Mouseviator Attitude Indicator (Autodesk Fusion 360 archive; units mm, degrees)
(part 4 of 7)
sketch "Board outlines" plane through (0, 39, 0) normal (0, 1, 0) x axis (1, 0, 0)
  line L1 (36.0921, -32.5978) -> (36.0921, 0.9022)
  line L2 (5.0921, -32.5978) -> (36.0921, -32.5978)
  line L3 (5.0921, 0.9022) -> (5.0921, -32.5978)
  line L4 (36.0921, 0.9022) -> (5.0921, 0.9022)
  line L5 (36.0921, 0.9022) -> (5.0921, -32.5978)
  line L6 (5.0921, 0.9022) -> (36.0921, -32.5978)
  line L7 (-0.4082, -32.5804) -> (-0.4082, 0.9196)
  line L8 (-31.4082, -32.5804) -> (-0.4082, -32.5804)
  line L9 (-31.4082, 0.9196) -> (-31.4082, -32.5804)
  line L10 (-0.4082, 0.9196) -> (-31.4082, 0.9196)
  line L11 (-0.4082, 0.9196) -> (-31.4082, -32.5804)
  line L12 (-31.4082, 0.9196) -> (-0.4082, -32.5804)
  line L13 (-36.4994, -34.1766) -> (-41.1157, -22.3885)
  line L14 (-26.5185, -40.8706) -> (-34.1546, -36.8093)
  line L15 (24.1231, -41.4655) -> (-24.1331, -41.4655)
  line L16 (33.6166, -37.0564) -> (26.5251, -40.8618)
  line L17 (41.1157, -22.3885) -> (36.4994, -34.1766)
  line L18 (41.4655, 20.5361) -> (41.4655, -20.5361)
  line L19 (36.4994, 34.1766) -> (41.1157, 22.3885)
  line L20 (23.2139, 41.1177) -> (33.6166, 37.0564)
  curve K1 (21.3665, 41.4655) -> (21.9088, 41.4365)
  line L21 (-28.9018, 41.4655) -> (21.3665, 41.4655)
  line L22 (-41.4655, -20.5361) -> (-41.4655, 28.9018)
  curve K2 (-41.4365, -21.0784) -> (-41.4655, -20.5361)
  line L23 (-40, -14) -> (-35, -14)
  line L24 (-40, 12) -> (-40, -14)
  line L25 (-35, 12) -> (-40, 12)
  line L26 (-35, -14) -> (-35, 12)
  line L27 (34.1616, 34.6741) -> (38.4785, 23.6504)
  line L28 (23.7487, 38.7393) -> (34.1616, 34.6741)
  line L29 (21.8646, 33.9133) -> (23.7487, 38.7393)
  line L30 (30.1616, 30.6741) -> (21.8646, 33.9133)
  line L31 (33.6522, 21.7604) -> (30.1616, 30.6741)
  line L32 (38.4785, 23.6504) -> (33.6522, 21.7604)
  circle C1 centre (7.0921, -1.0978) radius 1.375
  circle C2 centre (34.0921, -1.0978) radius 1.375
  circle C3 centre (34.0921, -30.5978) radius 1.375
  circle C4 centre (7.0921, -30.5978) radius 1.375
  circle C5 centre (-29.4082, -1.0804) radius 1.375
  circle C6 centre (-2.4082, -1.0804) radius 1.375
  circle C7 centre (-2.4082, -30.5804) radius 1.375
  circle C8 centre (-29.4082, -30.5804) radius 1.375
  circle C9 centre (-20, 14) radius 10
  circle C10 centre (18.76, 36.96) radius 1.4
  circle C11 centre (-37.3525, 16.6048) radius 1.4
  circle C12 centre (-18.76, -36.96) radius 1.4
  circle C13 centre (36.96, -18.76) radius 1.4
  circle C14 centre (18.76, -36.96) radius 1.4
  circle C15 centre (-36.96, -18.76) radius 1.4
  circle C16 centre (-17.3319, 36.9825) radius 1.4
  circle C17 centre (36.96, 18.76) radius 1.4
  arc A1 centre (-36.3855, -20.5361) radius 5.08 clockwise from (-41.1157, -22.3885) to (-41.4365, -21.0784)
  arc A2 centre (-31.7692, -32.3242) radius 5.08 clockwise from (-34.1546, -36.8093) to (-36.4994, -34.1766)
  arc A3 centre (-24.1331, -36.3855) radius 5.08 clockwise from (-24.1331, -41.4655) to (-26.5185, -40.8706)
  arc A4 centre (24.1231, -36.3855) radius 5.08 clockwise from (26.5251, -40.8618) to (24.1231, -41.4655)
  arc A5 centre (31.7692, -32.3242) radius 5.08 clockwise from (36.4994, -34.1766) to (33.6166, -37.0564)
  arc A6 centre (36.3855, -20.5361) radius 5.08 clockwise from (41.4655, -20.5361) to (41.1157, -22.3885)
  arc A7 centre (36.3855, 20.5361) radius 5.08 clockwise from (41.1157, 22.3885) to (41.4655, 20.5361)
  arc A8 centre (31.7692, 32.3242) radius 5.08 clockwise from (33.6166, 37.0564) to (36.4994, 34.1766)
  arc A9 centre (21.3665, 36.3855) radius 5.08 clockwise from (21.9088, 41.4365) to (23.2139, 41.1177)
  arc A10 centre (-28.9018, 28.9018) radius 12.5637 clockwise from (-41.4655, 28.9018) to (-28.9018, 41.4655)
  point P3 (36.0921, 0.9022)
  point P4 (5.0921, 0.9022)
  point P6 (5.0921, -32.5978)
  point P9 (7.0921, -1.0978)
  point P11 (-0.4082, 0.9196)
  point P12 (-31.4082, 0.9196)
  point P14 (-31.4082, -32.5804)
  point P17 (-29.4082, -1.0804)
  point P26 (36.96, 18.76)
  point P19 (18.76, 36.96)
  point P10 (-29.4082, -30.5804)
  point P16 (-2.4082, -30.5804)
  point P15 (-2.4082, -1.0804)
  point P7 (34.0921, -1.0978)
  point P8 (34.0921, -30.5978)
  point P2 (7.0921, -30.5978)
  perpendicular L2 L3
  parallel L2 L4
  parallel L1 L3
  horizontal L2
  perpendicular L8 L9
  parallel L8 L10
  parallel L7 L9
  horizontal L8
  horizontal L23
  vertical L24
  horizontal L25
  vertical L26
  parallel L19 L27
  parallel L20 L28
  perpendicular L28 L29
  perpendicular L29 L30
  parallel L27 L31
  perpendicular L31 L32
  dimension "d433_1" distance P3 P4 = 31
  dimension "d434_1" distance P4 P6 = 33.5
  dimension "d435_1" diameter C1 = 2.75
  dimension "d436_1" distance P9 L3 = 2
  dimension "d437_1" distance P9 L4 = 2
  dimension "d442_1" distance P11 P12 = 31
  dimension "d443_1" distance P12 P14 = 33.5
  dimension "d444_1" diameter C5 = 2.75
  dimension "d445_1" distance P17 L9 = 2
  dimension "d446_1" distance P17 L10 = 2
  dimension "d470_1" diameter C9 = 20
  dimension "d478_1" distance P26 L32 = 4
  dimension "d479_1" distance P19 L29 = 4
  dimension "d546" distance P10 L8 = 2
  dimension "d547" distance P16 L8 = 2
  dimension "d548" distance P16 L7 = 2
  dimension "d549" distance P10 L9 = 2
  dimension "d550" distance P15 L10 = 2
  dimension "d551" distance P15 L7 = 2
  dimension "d552" distance P7 L4 = 2
  dimension "d553" distance P7 L1 = 2
  dimension "d554" distance P8 L1 = 2
  dimension "d555" distance P8 L2 = 2
  dimension "d556" distance P2 L2 = 2
  dimension "d557" distance P2 L3 = 2
extrude "Extrude16" add sketch "Board outlines" profile of C1 C2 C3 C4 C5 C6 C7 C8 along normal blind 7 named "d473_1" Side1WallThickness 1.5 named "d472_1"
extrude "Extrude17" cut sketch "Board outlines" profile of C9 no distance stored
fillet "Fillet4" radius 1 named "d477_1"
extrude "Extrude18" add sketch "Board outlines" profile of L27 L28 L29 L30 L31 L32 along normal blind 10 named "d480_1"
extrude "Extrude19" add sketch "Board outlines" profile of L23 L24 L25 L26 along normal blind 10 named "d482_1"
sketch "VCC cutouts" plane through (-40, 0, 0) normal (-1, 0, 0) x axis (0, -1, 0)
  line L1 (-39, 14) -> (-39, -12)
  line L2 (-49, 14) -> (-39, 14)
  line L3 (-49, -12) -> (-49, 14)
  line L4 (-39, -12) -> (-49, -12)
  circle C1 centre (-44, 9) radius 3
  circle C2 centre (-44, -7) radius 3
  circle C3 centre (-44, 1) radius 3
  dimension "d484_1" diameter C1 = 6
  dimension "d485_1" diameter C2 = 6
  dimension "d486_1" diameter C3 = 6
extrude "Extrude20" cut sketch "VCC cutouts" profile of C1 C2 C3 against normal blind 6 named "d487_1"
sketch "Cable cutout 1" plane through (36.5661, 0, -14.3196) normal (-0.9311, 0, 0.3646) x axis (0, -1, 0)
  line L1 (-39, -7.991) -> (-39, -17.5638)
  line L2 (-49, -7.991) -> (-39, -7.991)
  line L3 (-49, -17.5638) -> (-49, -7.991)
  line L4 (-39, -17.5638) -> (-49, -17.5638)
  circle C1 centre (-44, -12.7774) radius 3.5
  dimension "d489_1" diameter C1 = 7
sketch "Cable cutout 2" plane through (14.3806, 0, -36.835) normal (-0.3637, 0, 0.9315) x axis (0, -1, 0)
  line L1 (-39, 16.941) -> (-39, 8.0341)
  line L2 (-49, 16.941) -> (-39, 16.941)
  line L3 (-49, 8.0341) -> (-49, 16.941)
  line L4 (-39, 8.0341) -> (-49, 8.0341)
  circle C1 centre (-44, 12.4876) radius 3.5
  dimension "d490_1" diameter C1 = 7
extrude "Extrude21" cut sketch "Cable cutout 1" profile of C1 no distance stored
extrude "Extrude22" cut sketch "Cable cutout 2" profile of C1 no distance stored
position "Position1"
sketch "Sketch5" plane through (0, 39, 0) normal (0, 1, 0) x axis (1, 0, 0)
  line L1 (-29.1716, 41.2776) -> (-25.502, 41.2776)
  line L2 (40.6918, -30.5858) -> (30.5858, -40.6918)
  line L3 (-30.5858, -40.6918) -> (-40.6918, -30.5858)
  line L4 (25.492, 41.2776) -> (29.1716, 41.2776)
  line L5 (-41.2776, -29.1716) -> (-41.2776, 29.1716)
  line L6 (41.2776, 29.1716) -> (41.2776, -29.1716)
  line L7 (-40.6918, 30.5858) -> (-30.5858, 40.6918)
  line L8 (29.1716, -41.2776) -> (-29.1716, -41.2776)
  line L9 (30.5858, 40.6918) -> (40.6918, 30.5858)
  line L10 (-24.1331, 41.4655) -> (24.1231, 41.4655)
  arc A1 centre (-29.1716, -39.2776) radius 2 clockwise from (-29.1716, -41.2776) to (-30.5858, -40.6918)
  circle C1 centre (18.76, 36.96) radius 1.4
  arc A2 centre (-39.2776, 29.1716) radius 2 clockwise from (-41.2776, 29.1716) to (-40.6918, 30.5858)
  circle C2 centre (36.96, 18.76) radius 1.4
  circle C3 centre (36.96, -18.76) radius 1.4
  arc A3 centre (-29.1716, 39.2776) radius 2 clockwise from (-30.5858, 40.6918) to (-29.1716, 41.2776)
  arc A4 centre (24.1231, 36.3855) radius 5.08 clockwise from (24.1231, 41.4655) to (25.492, 41.2776)
  circle C4 centre (-36.96, 18.76) radius 1.4
  arc A5 centre (39.2776, 29.1716) radius 2 clockwise from (40.6918, 30.5858) to (41.2776, 29.1716)
  circle C5 centre (-18.76, 36.96) radius 1.4
  arc A6 centre (29.1716, -39.2776) radius 2 clockwise from (30.5858, -40.6918) to (29.1716, -41.2776)
  arc A7 centre (-39.2776, -29.1716) radius 2 clockwise from (-40.6918, -30.5858) to (-41.2776, -29.1716)
  arc A8 centre (-24.1331, 36.3855) radius 5.08 clockwise from (-25.502, 41.2776) to (-24.1331, 41.4655)
  circle C6 centre (-18.76, -36.96) radius 1.4
  circle C7 centre (18.76, -36.96) radius 1.4
  arc A9 centre (39.2776, -29.1716) radius 2 clockwise from (41.2776, -29.1716) to (40.6918, -30.5858)
  arc A10 centre (29.1716, 39.2776) radius 2 clockwise from (29.1716, 41.2776) to (30.5858, 40.6918)
  circle C8 centre (-36.96, -18.76) radius 1.4
  point P3 (0, 0)
  point P5 (0, 0)
  point P4 (0, 0)
  coincident P3 P5
  coincident P3 P4
extrude "Extrude23" new body sketch "Sketch5" against normal blind 2.5
extrude "Extrude24" add sketch "Board outlines" profile of C1 C2 C3 C4 C5 C6 C7 C8 along normal blind 7 Side1WallThickness 1.5
extrude "Extrude25" cut sketch "Board outlines" profile of C9 no distance stored
fillet "Fillet5" radius 1
extrude "Extrude26" add sketch "Board outlines" profile of L23 L24 L25 L26 L27 L28 L29 L30 L31 L32 along normal blind 10
extrude "Extrude27" cut sketch "VCC cutouts" profile of C1 C2 C3 against normal blind 6
extrude "Extrude28" cut sketch "Cable cutout 1" profile of C1 no distance stored
extrude "Extrude29" cut sketch "Cable cutout 2" profile of C1 no distance stored
component_insert "Component Insert1"
component_insert "Component Insert2"
position "Position5"
position "Position6"
position "Position2"
sketch "Sketch4" plane through (0, -3.75, 0) normal (0, -1, 0) x axis (1, 0, 0)
  line L1 (-6.25, -30.75) -> (-6.25, -39.1543)
  line L2 (-10, -30.75) -> (-6.25, -30.75)
  line L3 (-10, -28.75) -> (-10, -30.75)
  line L4 (-6.25, -28.75) -> (-10, -28.75)
  line L5 (-6.25, -19.6098) -> (-6.25, -28.75)
  line L6 (-4.554, -16.3519) -> (-6.25, -19.6098)
  line L7 (-1.2, -16.3519) -> (-4.554, -16.3519)
  line L8 (-1.2, -12.6019) -> (-1.2, -16.3519)
  line L9 (-3.7293, -12.6019) -> (-1.2, -12.6019)
  line L10 (-9.5326, -23.75) -> (-3.7293, -12.6019)
  line L11 (-27.9134, -23.75) -> (-9.5326, -23.75)
  line L12 (-14.9494, 36.7238) -> (-14.1663, 33.8014)
  line L13 (-31.75, -23.75) -> (-27.9134, -23.75)
  arc A1 centre (0, 0) radius 36.65 clockwise from (-27.9134, -23.75) to (-14.1663, 33.8014)
  arc A2 centre (0, 0) radius 39.65 clockwise from (-6.25, -39.1543) to (-14.9494, 36.7238)
  point P13 (-27.9134, -23.75)
  point P17 (-27.9134, -23.75)
  point P18 (-31.75, -23.75)
  coincident P13 P17
  coincident A2 P18
  parallel L11 L13
sketch "Sketch5" plane through (0, -3.75, 0) normal (0, -1, 0) x axis (1, 0, 0)
  line L1 (6.25, -39.1543) -> (6.25, -30.75)
  line L2 (14.1663, 33.8014) -> (14.9494, 36.7238)
  line L3 (9.5326, -23.75) -> (27.9134, -23.75)
  line L4 (3.7293, -12.6019) -> (9.5326, -23.75)
  line L5 (1.2, -12.6019) -> (3.7293, -12.6019)
  line L6 (1.2, -16.3519) -> (1.2, -12.6019)
  line L7 (4.554, -16.3519) -> (1.2, -16.3519)
  line L8 (6.25, -19.6098) -> (4.554, -16.3519)
  line L9 (6.25, -28.75) -> (6.25, -19.6098)
  line L10 (10, -28.75) -> (6.25, -28.75)
  line L11 (10, -30.75) -> (10, -28.75)
  line L12 (6.25, -30.75) -> (10, -30.75)
  line L13 (31.75, -23.75) -> (27.9134, -23.75)
  arc A1 centre (0, 0) radius 39.65 clockwise from (14.9494, 36.7238) to (6.25, -39.1543)
  arc A2 centre (0, 0) radius 36.65 clockwise from (14.1663, 33.8014) to (27.9134, -23.75)
  point P7 (27.9134, -23.75)
  point P17 (27.9134, -23.75)
  point P18 (31.75, -23.75)
  coincident P7 P17
  coincident A1 P18
  parallel L3 L13
extrude "Extrude8" add sketch "Sketch4" profile of A1 L12 A2 L13 along normal blind 0.85
extrude "Extrude9" add sketch "Sketch5" profile of A1 L2 A2 L13 along normal blind 0.85
extrude "Extrude10" add of existing geometry blind 1
extrude "Extrude10" cut of existing geometry blind -0.5
extrude "Extrude11" cut of existing geometry blind -2.5
extrude "Extrude12" cut of existing geometry blind -0.5
extrude "Extrude13" cut of existing geometry blind -2
ground "Unpin4"
ground "Unpin5"
position "Position3"
ground "Pin6"
ground "Pin7"
position "Position4"
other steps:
derived_base_feature "Instrument Sketch"
derived_base_feature "Derived Base Feature1" sketch "Sketch2"
derived_base_feature "Analog Master"
derived_base_feature "Top Sketch" bodies "Top LED Holder"
derived_base_feature "Sketch1" bodies "Body1"
derived_base_feature "Derived Base Feature1" sketch "Sketch2" bodies "Body1", "Body2"
derived_base_feature "Derived Base Feature1" sketch "Sketch2" bodies "Body1", "Body2"
derived_base_feature "Top Sketch" bodies "Standard Bezel"
derived_base_feature "Derived Base Feature2" bodies "Standard Bezel (1)"
derived_base_feature "Sketch1" bodies "Seal"
extrude "Extrude3" cut sketch "Sketch1" profile of A1 L5 L6 L7 A2 C1 A3 L10 L12 C2 A6 L17 L18 L19 L20 L23 L24 L25 L26 L27 L28 L31 L32 L33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 along normal blind 3 (= "2 mm + 1 mm") and against normal blind 0.5
extrude "Extrude8" cut sketch "Left Arm" profile of C1 to an object
fillet "Fillet1" radius 1
create_component "CreateComponent1" sketch "Sketch2"
create_component "CreateComponent2"
create_component "CreateComponent3"
create_component "CreateComponent4"
create_component "CreateComponent5"
create_component "CreateComponent6"
create_component "CreateComponent7"
create_component "CreateComponent8" sketch "Sketch2"
create_component "CreateComponent9"
create_component "CreateComponent10"
create_component "CreateComponent11"
create_component "CreateComponent1"
create_component "CreateComponent2"
create_component "CreateComponent3"
joint_origin "JointOrigin4"
joint_origin "JointOrigin5"
joint_origin "JointOrigin7"
joint_origin "JointOrigin5"
remove_instance "RemoveInstance1"
extrude "Extrude1" cut sketch "Sketch2" profile of A1 A2 L1 L2 L3 L4 C1 L5 A3 L6 A4 A5 A6 blind -2 Side2Offset 0
extrude "Extrude1" cut sketch "Sketch2" profile of A1 A2 L1 L2 L3 L4 C1 L5 A3 L6 A4 A5 A6 blind -2 Side2Offset 0
joint_origin "JointOrigin1"
joint_origin "JointOrigin1"
create_component "CreateComponent1"
create_component "CreateComponent2"
create_component "CreateComponent4"
extrude "Extrude4" cut sketch "Sketch1" profile of A1 L5 L6 L7 A2 C1 A3 L10 L12 C2 A6 L17 L18 L19 L20 L23 L24 L25 L26 L27 L28 L31 L32 L33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 along normal blind 3 (= "2 mm + 1 mm") and against normal blind 0.5
extrude "Extrude2" cut sketch "Sketch1" profile of A1 L5 L6 L7 A2 C1 A3 L10 L12 C2 A6 L17 L18 L19 L20 L23 L24 L25 L26 L27 L28 L31 L32 L33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 along normal blind 3 (= "2 mm + 1 mm") and against normal blind 0.5
create_component "CreateComponent5"
remove_body "RemoveBody1"
create_component "CreateComponent6"
create_component "CreateComponent7"
create_component "CreateComponent8"
joint_origin "JointOrigin7"
joint_origin "JointOrigin6"
joint_origin "JointOrigin12"
create_component "CreateComponent1"
joint_origin "JointOrigin3"
joint_origin "JointOrigin8"
joint_origin "JointOrigin10"
joint_origin "JointOrigin12"
create_component "CreateComponent2"
create_component "CreateComponent12"
create_component "CreateComponent14"
named bodies: "Standard Bezel", "Body1", "Body2", "Seal", "Top LED Holder", "Standard Bezel (1)"

design "Bezel LED and Glass MS33638C" references "LED D5 - White-Clear"
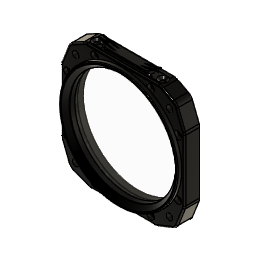
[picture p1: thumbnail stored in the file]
parameter "d52" = 0.15
canvas "Canvas4"
canvas "Canvas1"
sketch "Instrument Sketch" plane through (0, 0, 0) normal (1, 0, 0) x axis (0, 1, 0)
  line L1 (-41.4655, 20.5361) -> (-41.4655, 0)
  line L2 (-36.4994, 34.1766) -> (-41.1157, 22.3885)
  line L3 (-23.2139, 41.1177) -> (-33.6166, 37.0564)
  line L4 (0, 41.4655) -> (-21.3665, 41.4655)
  line L5 (0, 22.5) -> (0, 0)
  line L6 (0, 0) -> (0, 41.4655)
  line L7 (-41.4655, 0) -> (0, 0)
  line L8 (41.4655, 20.5361) -> (41.4655, 0)
  line L9 (36.4994, 34.1766) -> (41.1157, 22.3885)
  line L10 (23.2139, 41.1177) -> (33.6166, 37.0564)
  line L11 (0, 41.4655) -> (21.3665, 41.4655)
  line L12 (-41.4655, -20.5361) -> (-41.4655, 0)
  line L13 (-36.4994, -34.1766) -> (-41.1157, -22.3885)
  line L14 (-23.2139, -41.1177) -> (-33.6166, -37.0564)
  line L15 (0, -41.4655) -> (-21.3665, -41.4655)
  line L16 (41.4655, -20.5361) -> (41.4655, 0)
  line L17 (36.4994, -34.1766) -> (41.1157, -22.3885)
  line L18 (0, -41.4655) -> (21.3665, -41.4655)
  line L19 (23.2139, -41.1177) -> (33.6166, -37.0564)
  line L20 (-1.0967, 0) -> (0, 0)
  line L21 (-72.2485, 72.2485) -> (0, 0)
  line L22 (24.1231, 41.4655) -> (-24.1331, 41.4655)
  line L23 (26.5251, 40.8618) -> (33.6166, 37.0564)
  line L24 (-34.1546, 36.8093) -> (-26.5185, 40.8706)
  circle C1 centre (0, 0) radius 39.6875
  circle C2 centre (31.4309, 31.4309) radius 2.159
  circle C3 centre (-31.4309, -31.4309) radius 2.159
  circle C4 centre (-31.4309, 31.4309) radius 2.159
  circle C5 centre (31.4309, -31.4309) radius 2.159
  arc A1 centre (-31.7692, 32.3242) radius 5.08 clockwise from (-36.4994, 34.1766) to (-33.6166, 37.0564)
  arc A2 centre (-21.3665, 36.3855) radius 5.08 clockwise from (-23.2139, 41.1177) to (-21.3665, 41.4655)
  arc A3 centre (-36.3855, 20.5361) radius 5.08 clockwise from (-41.4655, 20.5361) to (-41.1157, 22.3885)
  arc A4 centre (36.3855, 20.5361) radius 5.08 clockwise from (41.1157, 22.3885) to (41.4655, 20.5361)
  arc A5 centre (31.7692, 32.3242) radius 5.08 clockwise from (33.6166, 37.0564) to (36.4994, 34.1766)
  arc A6 centre (21.3665, 36.3855) radius 5.08 clockwise from (21.3665, 41.4655) to (23.2139, 41.1177)
  arc A7 centre (-36.3855, -20.5361) radius 5.08 clockwise from (-41.1157, -22.3885) to (-41.4655, -20.5361)
  arc A8 centre (-31.7692, -32.3242) radius 5.08 clockwise from (-33.6166, -37.0564) to (-36.4994, -34.1766)
  arc A9 centre (-21.3665, -36.3855) radius 5.08 clockwise from (-21.3665, -41.4655) to (-23.2139, -41.1177)
  arc A10 centre (36.3855, -20.5361) radius 5.08 clockwise from (41.4655, -20.5361) to (41.1157, -22.3885)
  arc A11 centre (31.7692, -32.3242) radius 5.08 clockwise from (36.4994, -34.1766) to (33.6166, -37.0564)
  arc A12 centre (21.3665, -36.3855) radius 5.08 clockwise from (23.2139, -41.1177) to (21.3665, -41.4655)
  circle C6 centre (0, 0) radius 35.5256
  arc A13 centre (-24.1331, 36.3855) radius 5.08 clockwise from (-26.5185, 40.8706) to (-24.1331, 41.4655)
  arc A14 centre (24.1231, 36.3855) radius 5.08 clockwise from (24.1231, 41.4655) to (26.5251, 40.8618)
  point P1 (0, 0)
  point P2 (0, 0)
  point P13 (0, 0)
  point P3 (-41.4655, 0)
  point P23 (41.4655, 0)
  point P4 (0, 41.4655)
  point P33 (0, 41.4655)
  point P14 (-36.4994, 34.1766)
  point P27 (36.4994, 34.1766)
  point P15 (-33.6166, 37.0564)
  point P29 (33.6166, 37.0564)
  point P17 (-23.2139, 41.1177)
  point P30 (23.2139, 41.1177)
  point P18 (-21.3665, 41.4655)
  point P32 (21.3665, 41.4655)
  point P20 (-41.4655, 20.5361)
  point P24 (41.4655, 20.5361)
  point P21 (-41.1157, 22.3885)
  point P26 (41.1157, 22.3885)
  point P34 (-41.4655, 0)
  point P44 (0, -41.4655)
  point P38 (-36.4994, -34.1766)
  point P40 (-33.6166, -37.0564)
  point P41 (-23.2139, -41.1177)
  point P43 (-21.3665, -41.4655)
  point P35 (-41.4655, -20.5361)
  point P37 (-41.1157, -22.3885)
  point P45 (41.4655, 0)
  point P46 (41.4655, -20.5361)
  point P48 (41.1157, -22.3885)
  point P49 (36.4994, -34.1766)
  point P51 (33.6166, -37.0564)
  point P53 (23.2139, -41.1177)
  point P54 (21.3665, -41.4655)
  point P55 (0, -41.4655)
  point P57 (0, 0)
  point P58 (-1.0967, 0)
  point P56 (0, 0)
  point P59 (0, 0)
  point P6 (0, 0)
  point P63 (0, 41.4655)
  point P64 (-34.1546, 36.8093)
  point P61 (-25.4, 41.4655)
  point P62 (25.4, 41.4655)
  coincident P1 P2
  vertical L1
  horizontal L4
  equal C3 C4
  equal C3 C5
  equal C2 C5
  coincident P1 P13
  perpendicular L1 L7
  tangent L2 A1
  tangent L3 A1
  tangent L3 A2
  tangent L4 A2
  equal A1 A2
  tangent L1 A3
  tangent L2 A3
  equal A1 A3
  symmetric P3 L6 P23
  symmetric P4 L6 P33
  symmetric L6 P14 P27
  symmetric L6 P15 P29
  symmetric L6 A1 A5
  symmetric L6 P17 P30
  symmetric L6 P18 P32
  symmetric L6 A2 A6
  symmetric L6 P20 P24
  symmetric L6 P21 P26
  symmetric L6 A3 A4
  symmetric P3 L7 P34
  symmetric P4 L7 P44
  symmetric L7 P14 P38
  symmetric L7 P15 P40
  symmetric L7 A1 A8
  symmetric L7 P17 P41
  symmetric L7 P18 P43
  symmetric L7 A2 A9
  symmetric L7 P20 P35
  symmetric L7 P21 P37
  symmetric L7 A3 A7
  symmetric L7 P23 P45
  symmetric L7 P24 P46
  symmetric L7 P26 P48
  symmetric L7 A4 A10
  symmetric L7 P27 P49
  symmetric L7 P29 P51
  symmetric L7 A5 A11
  symmetric L7 P30 P53
  symmetric L7 P32 P54
  symmetric L7 A6 A12
  symmetric L7 P33 P55
  coincident P23 P45
  coincident P1 P57
  coincident L7 P58
  perpendicular L6 L20
  coincident P56 P59
  coincident P6 P56
  perpendicular L6 L22
  coincident P33 P63
  coincident A1 P64
  tangent A1 L24
  coincident L22 P63
  coincident P61 L24
  coincident P61 L22
  tangent L24 A13
  tangent L22 A13
  coincident P62 L23
  coincident P62 L22
  tangent L23 A14
  tangent L22 A14
  equal A13 A14
  dimension "d1" diameter C1 = 79.375 (= "3 1/8")
  dimension "d2" radius A1 = 5.08 (= "0.20")
  dimension "d10" = 82.931 (= "3.265")
  dimension "d11" = 82.931 (= "d10")
  dimension "d13" angle L6 L21 = 45 (= "Angular Dimension-2")
  dimension "d58" distance P61 P62 = 50.8 (= "2")
  dimension "d59" radius A13 = 5.08
extrude "Extrude1" new body sketch "Instrument Sketch" profile of C1 L1 L2 L3 L4 C2 C3 C4 C5 A1 A2 A3 L8 A4 L9 A5 L10 A6 L11 L12 A7 L13 A8 L14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 along normal blind 10.25
extrude "Extrude2" sketch "Instrument Sketch" profile of C1 C6 blind 3
chamfer "Chamfer1" distance 3
canvas "Canvas2"
canvas "Canvas3"
move "Move1"
fillet "Fillet1" radius 0.5 0.5969 (= "0.047   * 0.5")
fillet "Fillet2" radius 1
sketch "Sketch2" plane through (0, 2, 0) normal (0, 1, 0) x axis (-1, 0, 0)
  line L1 (-36.4994, -34.1766) -> (-41.1157, -22.3885)
  line L2 (-23.2139, -41.1177) -> (-33.6166, -37.0564)
  line L3 (21.3665, -41.4655) -> (-21.3665, -41.4655)
  line L4 (33.6166, -37.0564) -> (23.2139, -41.1177)
  line L5 (41.1157, -22.3885) -> (36.4994, -34.1766)
  line L6 (41.4655, 20.5361) -> (41.4655, -20.5361)
  line L7 (36.4994, 34.1766) -> (41.1157, 22.3885)
  line L8 (-24.1231, 41.4655) -> (24.1331, 41.4655)
  line L9 (-41.1157, 22.3885) -> (-36.4994, 34.1766)
  line L10 (-41.4655, -20.5361) -> (-41.4655, 20.5361)
  line L11 (0, 32.0284) -> (0, 40.649)
  line L12 (-1.5, -39.15) -> (1.5, -39.15)
  line L13 (-1.5, -41.65) -> (-1.5, -39.15)
  line L14 (1.5, -41.65) -> (-1.5, -41.65)
  line L15 (1.5, -39.15) -> (1.5, -41.65)
  line L16 (-1.5, -41.65) -> (1.5, -39.15)
  line L17 (1.5, -41.65) -> (-1.5, -39.15)
  line L18 (26.5185, 40.8706) -> (34.1546, 36.8093)
  line L19 (-33.6166, 37.0564) -> (-26.5251, 40.8618)
  circle C1 centre (-31.4309, -31.4309) radius 2.159
  circle C2 centre (31.4309, 31.4309) radius 2.159
  circle C3 centre (31.4309, -31.4309) radius 2.159
  circle C4 centre (-31.4309, 31.4309) radius 2.159
  circle C5 centre (0, 0) radius 35.5256
  arc A1 centre (-36.3855, -20.5361) radius 5.08 clockwise from (-41.1157, -22.3885) to (-41.4655, -20.5361)
  arc A2 centre (-31.7692, -32.3242) radius 5.08 clockwise from (-33.6166, -37.0564) to (-36.4994, -34.1766)
  arc A3 centre (-21.3665, -36.3855) radius 5.08 clockwise from (-21.3665, -41.4655) to (-23.2139, -41.1177)
  arc A4 centre (21.3665, -36.3855) radius 5.08 clockwise from (23.2139, -41.1177) to (21.3665, -41.4655)
  arc A5 centre (31.7692, -32.3242) radius 5.08 clockwise from (36.4994, -34.1766) to (33.6166, -37.0564)
  arc A6 centre (36.3855, -20.5361) radius 5.08 clockwise from (41.4655, -20.5361) to (41.1157, -22.3885)
  arc A7 centre (36.3855, 20.5361) radius 5.08 clockwise from (41.1157, 22.3885) to (41.4655, 20.5361)
  arc A8 centre (31.7692, 32.3242) radius 5.08 clockwise from (34.1546, 36.8093) to (36.4994, 34.1766)
  arc A9 centre (-31.7692, 32.3242) radius 5.08 clockwise from (-36.4994, 34.1766) to (-33.6166, 37.0564)
  arc A10 centre (-36.3855, 20.5361) radius 5.08 clockwise from (-41.4655, 20.5361) to (-41.1157, 22.3885)
  circle C6 centre (0, 0) radius 39.65
  arc A11 centre (24.1331, 36.3855) radius 5.08 clockwise from (24.1331, 41.4655) to (26.5185, 40.8706)
  arc A12 centre (-24.1231, 36.3855) radius 5.08 clockwise from (-26.5251, 40.8618) to (-24.1231, 41.4655)
  point P1 (0, 0)
  point P39 (0, 0)
  point P41 (0, 32.0284)
  point P42 (0, 35.3825)
  point P43 (0.742, 39.6431)
  point P48 (0, -40.4)
  point P46 (-1.5, -41.65)
  point P47 (1.5, -41.65)
  point P45 (-1.5, -39.15)
  coincident P1 P39
  vertical L11
  vertical P39 P41
  coincident L11 P42
  coincident C6 P43
  horizontal L12
  perpendicular L12 L13
  parallel L12 L14
  parallel L13 L15
  coincident L16 P48
  coincident L17 P48
  vertical P1 P48
  dimension "d19" diameter C6 = 79.3
  dimension "d50" distance P46 P47 = 3
  dimension "d51" distance P45 P46 = 2.5
  dimension "d67" distance C6 L14 = 2
extrude "Extrude3" cut sketch "Sketch2" profile of C5 C6 L12 L13 L14 L15 to an object offset -6.5
sketch "Sketch1" plane through (0, -4.75, 0) normal (0, 1, 0) x axis (-1, 0, 0)
  line L1 (0, 40.6) -> (0.6381, 39.4948)
  line L2 (-0.6381, 39.4948) -> (0, 40.6)
  line L3 (1.5, -39.6216) -> (1.5, -41.4655)
  line L4 (-1.5, -41.4655) -> (-1.5, -39.6216)
  line L5 (1.5, -41.4655) -> (-1.5, -41.4655)
  circle C1 centre (0, 0) radius 35.5256
  circle C2 centre (0, 0) radius 39.55
  arc A1 centre (0, 0) radius 39.65 clockwise from (-1.5, -39.6216) to (1.5, -39.6216)
  arc A2 centre (0, 0) radius 39.5 clockwise from (0.6381, 39.4948) to (-0.6381, 39.4948)
  point P1 (0, 0)
  point P3 (0, 0)
  coincident P1 P3
  concentric A1 A2
extrude "Extrude1" new body sketch "Sketch1" profile of C1 C2 A1 L1 L2 A2 L3 L4 along normal blind 3
sketch "Sketch1" plane through (0, -1.75, 0) normal (0, 1, 0) x axis (-1, 0, 0)
  line L1 (-1.5, -39.6216) -> (-1.5, -41.4655)
  line L2 (1.5, -41.4655) -> (1.5, -39.6216)
  line L3 (1.5, -41.15) -> (-1.5, -41.15)
  line L4 (1.35, -38.7521) -> (1.35, -39.6216)
  line L5 (-1.35, -38.2133) -> (-1.35, -39.6216)
  line L6 (-1.35, -41.3) -> (-1.35, -41.4655)
  line L7 (-1.35, -39.6216) -> (-1.35, -41.3)
  line L8 (-1.35, -41.3) -> (-1.5, -41.3)
  line L9 (1.35, -41.3) -> (-1.35, -41.3)
  line L10 (1.5, -41.3) -> (1.35, -41.3)
  line L11 (1.35, -41.4655) -> (1.35, -41.3)
  line L12 (1.35, -41.3) -> (1.35, -39.6216)
  circle C1 centre (0, 0) radius 39.65
  circle C2 centre (0, 0) radius 36.65
  circle C3 centre (0, 0) radius 39.5
  parallel L4 L12
  parallel L5 L7
  dimension "d25" diameter C1 = 79.3
  dimension "d29" = -3
  dimension "d68" = -0.15
  dimension "d69" = 0.15
extrude "Extrude1" new body sketch "Sketch1" profile of C1 C2 C3 L7 L10 L12 L4 L5 to an object bodies "Seal"
sketch "Panel Sketch" plane through (0, -8.25, 0) normal (0, -1, 0) x axis (1, 0, 0)
  line L1 (-40.1846, 22.0238) -> (-35.5682, 33.812)
  line L2 (-40.4655, -20.5361) -> (-40.4655, 20.5361)
  line L3 (-35.5682, -33.812) -> (-40.1846, -22.0238)
  line L4 (-22.8502, -40.1861) -> (-33.2529, -36.1249)
  line L5 (21.3665, -40.4655) -> (-21.3665, -40.4655)
  line L6 (33.2529, -36.1249) -> (22.8502, -40.1861)
  line L7 (40.1846, -22.0238) -> (35.5682, -33.812)
  line L8 (40.4655, 20.5361) -> (40.4655, -20.5361)
  line L9 (35.5682, 33.812) -> (40.1846, 22.0238)
  line L10 (-24.1331, 40.4655) -> (24.1231, 40.4655)
  line L11 (26.0523, 39.9806) -> (33.1998, 36.1452)
  line L12 (-33.685, 35.9265) -> (-26.049, 39.9877)
  circle C1 centre (31.4309, 31.4309) radius 2.159
  circle C2 centre (-31.4309, -31.4309) radius 2.159
  circle C3 centre (-31.4309, 31.4309) radius 2.159
  circle C4 centre (31.4309, -31.4309) radius 2.159
  circle C5 centre (0, 0) radius 39.6875
  arc A1 centre (-36.3855, 20.5361) radius 4.08 clockwise from (-40.4655, 20.5361) to (-40.1846, 22.0238)
  arc A2 centre (-36.3855, -20.5361) radius 4.08 clockwise from (-40.1846, -22.0238) to (-40.4655, -20.5361)
  arc A3 centre (-31.7692, -32.3242) radius 4.08 clockwise from (-33.2529, -36.1249) to (-35.5682, -33.812)
  arc A4 centre (-21.3665, -36.3855) radius 4.08 clockwise from (-21.3665, -40.4655) to (-22.8502, -40.1861)
  arc A5 centre (21.3665, -36.3855) radius 4.08 clockwise from (22.8502, -40.1861) to (21.3665, -40.4655)
  arc A6 centre (31.7692, -32.3242) radius 4.08 clockwise from (35.5682, -33.812) to (33.2529, -36.1249)
  arc A7 centre (36.3855, -20.5361) radius 4.08 clockwise from (40.4655, -20.5361) to (40.1846, -22.0238)
  arc A8 centre (36.3855, 20.5361) radius 4.08 clockwise from (40.1846, 22.0238) to (40.4655, 20.5361)
  arc A9 centre (31.7692, 32.3242) radius 4.08 clockwise from (33.1998, 36.1452) to (35.5682, 33.812)
  arc A10 centre (-31.7692, 32.3242) radius 4.08 clockwise from (-35.5682, 33.812) to (-33.685, 35.9265)
  arc A11 centre (24.1231, 36.3855) radius 4.08 clockwise from (24.1231, 40.4655) to (26.0523, 39.9806)
  arc A12 centre (-24.1331, 36.3855) radius 4.08 clockwise from (-26.049, 39.9877) to (-24.1331, 40.4655)
sketch "Clamping Holes" plane through (0, -8.25, 0) normal (0, -1, 0) x axis (1, 0, 0)
  line L1 (0, 17.2297) -> (0, 0)
  line L2 (-22.2137, 0) -> (0, 0)
  circle C1 centre (-36.96, 18.76) radius 1
  circle C2 centre (36.96, 18.76) radius 1
  circle C3 centre (-36.96, -18.76) radius 1
  circle C4 centre (36.96, -18.76) radius 1
  circle C5 centre (-18.76, 36.96) radius 1
  circle C6 centre (18.76, 36.96) radius 1
  circle C7 centre (18.76, -36.96) radius 1
  circle C8 centre (-18.76, -36.96) radius 1
  point P1 (0, 0)
  point P3 (0, 0)
  point P5 (0, 0)
  point P2 (-36.96, 18.76)
  point P10 (-18.76, 36.96)
  coincident P1 P3
  vertical L1
  coincident P1 P5
  perpendicular L1 L2
  symmetric C1 L1 C2
  symmetric C1 L2 C3
  symmetric L2 C2 C4
  symmetric L1 C5 C6
  symmetric L2 C5 C8
  symmetric L2 C6 C7
  dimension "d32" diameter C1 = 2
  dimension "d33" distance P1 P2 = 18.76 (= "( 37.52 / 2 ) * 1 mm")
  dimension "d34" distance P1 P2 = 36.96 (= "( 73.92 / 2 ) * 1 mm")
  dimension "d37" diameter C5 = 2 (= "d32")
  dimension "d38" distance P1 P10 = 36.96 (= "d34")
  dimension "d39" distance P1 P10 = 18.76 (= "d33")
hole "Hole1" HoleDepth 10.25 HoleDiameter 2.8 CBDepth 2.5 CBDiameter 5
component_from_bodies "Body->Comp"
sketch "Top Sketch" plane through (0, 0, 41.4655) normal (0, 0, 1) x axis (-1, 0, 0)
  line L1 (-24.1231, 7.25) -> (24.1331, 7.25)
  line L2 (24.1331, -2) -> (-24.1231, -2)
  line L3 (-22.19, 6.25) -> (22.19, 6.25)
  line L4 (22.19, 0.25) -> (-22.19, 0.25)
  line L5 (-22.19, 3.25) -> (22.19, 3.25)
  line L6 (-24.1231, 8.25) -> (24.1331, 8.25)
  line L7 (-24.1231, -2) -> (-24.1231, 7.25)
  line L8 (24.1331, 7.25) -> (24.1331, -2)
  line L9 (22.19, 0.1) -> (-22.19, 0.1)
  line L10 (-22.19, 6.4) -> (22.19, 6.4)
  line L11 (-15.15, 0.1) -> (15.15, 0.1)
  line L12 (-15.15, 6.4) -> (-15.15, 0.1)
  line L13 (15.15, 6.4) -> (-15.15, 6.4)
  line L14 (15.15, 0.1) -> (15.15, 6.4)
  line L15 (-15.15, 6.4) -> (15.15, 0.1)
  line L16 (15.15, 6.4) -> (-15.15, 0.1)
  arc A1 centre (-22.19, 3.25) radius 3 clockwise from (-22.19, 0.25) to (-22.19, 6.25)
  arc A2 centre (22.19, 3.25) radius 3 clockwise from (22.19, 6.25) to (22.19, 0.25)
  arc A3 centre (22.19, 3.25) radius 3.15 clockwise from (22.19, 6.4) to (22.19, 0.1)
  arc A4 centre (-22.19, 3.25) radius 3.15 clockwise from (-22.19, 0.1) to (-22.19, 6.4)
  point P12 (0, 3.25)
  point P1 (0, 0)
  point P21 (15.15, 0.1)
  point P25 (0, 3.25)
  point P11 (-22.19, 3.25)
  point P10 (22.19, 3.25)
  point P23 (-15.15, 6.4)
  point P24 (15.15, 6.4)
  tangent L3 A1
  tangent A1 L4
  parallel L3 L4
  tangent L4 A2
  tangent L3 A2
  horizontal L5
  midpoint L5 P12
  vertical P1 P12
  horizontal L11
  perpendicular L11 L12
  parallel L11 L13
  parallel L12 L14
  coincident L9 P21
  coincident L15 P25
  coincident L16 P25
  coincident P12 P25
  dimension "d54" diameter A1 = 6
  dimension "d56" distance P11 L6 = 5
  dimension "d57" distance P10 P11 = 44.38
  dimension "d60" = 0.15
  dimension "d70" distance P23 P24 = 30.3
extrude "Extrude2" cut sketch "Top Sketch" profile of L3 A1 L4 A2 L9 L10 A3 A4 against normal blind 1.7
extrude "Extrude2" cut sketch "Top Sketch" profile of L3 L4 L9 L10 L11 L12 L13 L14 to an object
work_plane "WorkPlane1"
sketch "LED Angle" plane through (0, -3.25, 41.4655) normal (0, -1, 0) x axis (1, 0, 0)
  line L1 (14.8802, -5) -> (-0.0147, -1.0089)
  line L2 (50, -10.3752) -> (0, -10.3752)
  line L3 (0, 22.6624) -> (0, -10.6292)
  line L4 (-14.8802, -5) -> (-0.0147, -1.0089)
  line L5 (-24.1331, 0) -> (24.1231, 0)
  point P1 (0, 0)
  point P2 (0, -10.6292)
  point P3 (14.8802, -5)
  point P8 (-14.8802, -5)
  horizontal L2
  vertical P1 P2
  perpendicular L2 L3
  symmetric P3 L3 P8
  dimension "d104" angle L1 L2 = 15 (= "Angular Dimension-2")
  dimension "d106" distance P3 L5 = 5
pipe "Pipe2" SectionSize 6.5 SectionThickness 1.375
component_insert "Component Insert"
joint "Assemble1" alignOffsetX 0 alignOffsetY 0 alignOffsetZ -3
copy_paste "CutPaste"
work_plane "WorkPlane1"
mirror_component "MirrorComponent1"
derived_instance "DerivedInstance1"
mirror "Mirror1" mirrorStitchTolerance 0.1
extrude "Extrude1" new body sketch "Top Sketch" profile of L3 A1 L4 A2 L12 L14 against normal blind 1.7 bodies "Top LED Holder"
sketch "Top Sketch" plane through (0, 0, 41.4655) normal (0, 0, 1) x axis (-1, 0, 0)
  line L1 (-22.19, 6.25) -> (22.19, 6.25)
  line L2 (22.19, 0.25) -> (-22.19, 0.25)
  line L3 (0, 6.25) -> (0, 0.25)
  line L4 (-12.5, 6.225) -> (12.5, 6.225)
  line L5 (12.5, 0.275) -> (-12.5, 0.275)
  line L6 (-12.5, 3.25) -> (12.5, 3.25)
  line L7 (-13.6, 7.15) -> (13.6, 7.15)
  line L8 (13.6, -0.65) -> (-13.6, -0.65)
  line L9 (-13.6, 3.25) -> (13.6, 3.25)
  arc A1 centre (22.19, 3.25) radius 3 clockwise from (22.19, 6.25) to (22.19, 0.25)
  arc A2 centre (-22.19, 3.25) radius 3 clockwise from (-22.19, 0.25) to (-22.19, 6.25)
  arc A3 centre (-12.5, 3.25) radius 2.975 clockwise from (-12.5, 0.275) to (-12.5, 6.225)
  arc A4 centre (12.5, 3.25) radius 2.975 clockwise from (12.5, 6.225) to (12.5, 0.275)
  arc A5 centre (-13.6, 3.25) radius 3.9 clockwise from (-13.6, -0.65) to (-13.6, 7.15)
  arc A6 centre (13.6, 3.25) radius 3.9 clockwise from (13.6, 7.15) to (13.6, -0.65)
  circle C1 centre (-15.475, 3.25) radius 2.5
  circle C2 centre (15.475, 3.25) radius 2.5
  circle C3 centre (16.5801, 3.25) radius 1.5
  point P8 (0, 0.25)
  point P9 (0, 6.25)
  point P16 (0, 3.25)
  point P22 (-13.6, 3.25)
  point P23 (0, 3.25)
  point P24 (-15.475, 3.25)
  point P25 (15.475, 3.25)
  point P26 (16.5801, 3.25)
  midpoint L2 P8
  midpoint L1 P9
  tangent L4 A3
  tangent A3 L5
  parallel L4 L5
  tangent L5 A4
  tangent L4 A4
  perpendicular L3 L6
  midpoint L3 P16
  midpoint L6 P16
  tangent L7 A5
  tangent A5 L8
  parallel L7 L8
  tangent L8 A6
  tangent L7 A6
  coincident L6 P22
  parallel L6 L9
  coincident P16 P23
  midpoint L9 P23
  midpoint A3 P24
  midpoint A4 P25
  horizontal P23 P26
  dimension "d115" distance L4 L5 = 5.95
  dimension "d116" = 30.95
  dimension "d117" distance L7 L8 = 7.8
  dimension "d118" = 35
  dimension "d123" diameter C2 = 5
  dimension "d124" diameter C1 = 5 (= "d123")
  dimension "d126" diameter C3 = 3
extrude "Extrude2" add sketch "Top Sketch" profile of L4 A3 L5 A4 C1 C2 C3 along normal blind 2
extrude "Extrude3" add sketch "Top Sketch" profile of L1 L2 L4 A3 L5 A4 L7 A5 L8 A6 C1 C2 along normal blind 1
chamfer "Chamfer1" distance 0.8
extrude "Extrude4" cut sketch "Top Sketch" profile of A4 A6 C2 C3 to an object
sketch "Bottom Sketch" plane through (0, 0, 39.7655) normal (0, 0, -1) x axis (1, 0, 0)
  line L1 (22.19, 0.25) -> (-22.19, 0.25)
  line L2 (-22.19, 6.25) -> (22.19, 6.25)
  line L3 (9, 0.25) -> (-9, 0.25)
  line L4 (-9, 6.25) -> (9, 6.25)
  line L5 (9, 3.25) -> (-9, 3.25)
  line L6 (-11.5981, 4.75) -> (-16.5801, 4.75)
  line L7 (-11.5981, 1.75) -> (-11.5981, 4.75)
  line L8 (-16.5801, 1.75) -> (-11.5981, 1.75)
  line L9 (-16.5801, 4.75) -> (-16.5801, 1.75)
  circle C1 centre (-16.5801, 3.25) radius 1.5
  arc A1 centre (-22.19, 3.25) radius 3 clockwise from (-22.19, 0.25) to (-22.19, 6.25)
  arc A2 centre (22.19, 3.25) radius 3 clockwise from (22.19, 6.25) to (22.19, 0.25)
  circle C2 centre (-16.5801, 3.25) radius 1
  arc A3 centre (9, 3.25) radius 3 clockwise from (9, 6.25) to (9, 0.25)
  arc A4 centre (-9, 3.25) radius 3 clockwise from (-9, 0.25) to (-9, 6.25)
  point P16 (0, 3.25)
  point P19 (-11.5981, 1.75)
  point P17 (-16.5801, 4.75)
  point P20 (-16.5801, 1.75)
  point P9 (-16.5801, 3.25)
  point P1 (0, 0)
  point P15 (9, 3.25)
  concentric C1 C2
  tangent L3 A3
  tangent A3 L4
  parallel L3 L4
  tangent L4 A4
  tangent L3 A4
  parallel L1 L5
  midpoint L5 P16
  horizontal L6
  vertical L7
  horizontal L8
  vertical L9
  coincident A4 P19
  coincident C1 P17
  coincident C1 P20
  vertical P9 P20
  vertical P1 P16
  horizontal P9 P16
  dimension "d129" diameter A3 = 6
  dimension "d130" distance P15 P16 = 9
extrude "Extrude5" cut sketch "Bottom Sketch" profile of C1 L1 L2 L3 A3 L4 A4 L6 L7 L8 against normal blind 1
extrude "Extrude6" cut sketch "Bottom Sketch" profile of L1 L2 L3 A3 L4 A4 L7 against normal blind 2.5
work_plane "WorkPlane1"
hole "Hole1" HoleDepth 7 HoleDiameter 3.2 CSDiameter 6.3
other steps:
derived_base_feature "Derived Base Feature"
pipe "Pipe2" SectionSize 6.5 SectionThickness 1.375
mirror "Mirror1" mirrorStitchTolerance 0.1
base_feature "Base Feature" bodies "Standard Bezel"
extrude "Extrude1" cut sketch "Top Sketch" profile of L3 A1 L4 A2 L9 L10 A3 A4 against normal blind 1.7
pipe "Pipe2" SectionSize 6.5 SectionThickness 1.375
mirror "Mirror1" mirrorStitchTolerance 0.1
hole "Hole1" HoleDepth 7 HoleDiameter 3.2 CSDiameter 6.3
create_component "CreateComponent1"
create_component "CreateComponent2"
create_component "CreateComponent4"
remove_body "RemoveBody1"
extrude "Extrude2" cut sketch "Top Sketch" profile of L3 A1 L4 A2 L9 L10 A3 A4 against normal blind 1.7
joint_origin "JointOrigin1"
create_component "CreateComponent5"
remove_instance "RemoveInstance1"
create_component "CreateComponent1"
create_component "CreateComponent6"
named bodies: "Standard Bezel", "Seal", "Top LED Holder"

design "Hall Effect Sensor SS494B"
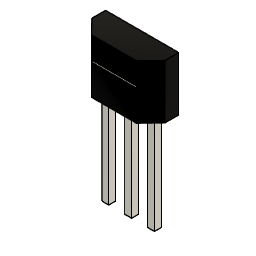
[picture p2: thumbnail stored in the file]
sketch "Top Profile" plane through (0, 0, 0) normal (0, 0, 1) x axis (1, 0, 0)
  line L1 (-2.03, -0.785) -> (2.03, -0.785)
  line L2 (-2.03, 0.785) -> (-2.03, -0.785)
  line L3 (2.03, 0.785) -> (-2.03, 0.785)
  line L4 (2.03, -0.785) -> (2.03, 0.785)
  line L5 (-2.03, 0.785) -> (2.03, -0.785)
  line L6 (2.03, 0.785) -> (-2.03, -0.785)
  line L7 (-2.03, 0.025) -> (-1.25, -0.785)
  line L8 (0, 0.785) -> (0, 0)
  line L9 (2.03, 0.025) -> (1.25, -0.785)
  line L10 (-1.46, 0.01) -> (-1.08, 0.01)
  line L11 (-1.46, 0.39) -> (-1.46, 0.01)
  line L12 (-1.08, 0.39) -> (-1.46, 0.39)
  line L13 (-1.08, 0.01) -> (-1.08, 0.39)
  line L14 (-1.46, 0.39) -> (-1.08, 0.01)
  line L15 (-1.08, 0.39) -> (-1.46, 0.01)
  line L16 (-0.19, 0.01) -> (0.19, 0.01)
  line L17 (-0.19, 0.39) -> (-0.19, 0.01)
  line L18 (0.19, 0.39) -> (-0.19, 0.39)
  line L19 (0.19, 0.01) -> (0.19, 0.39)
  line L20 (-0.19, 0.39) -> (0.19, 0.01)
  line L21 (0.19, 0.39) -> (-0.19, 0.01)
  line L22 (1.46, 0.01) -> (1.08, 0.01)
  line L23 (1.46, 0.39) -> (1.46, 0.01)
  line L24 (1.08, 0.39) -> (1.46, 0.39)
  line L25 (1.08, 0.01) -> (1.08, 0.39)
  point P6 (0, 0)
  point P1 (0, 0)
  point P7 (-1.25, -0.785)
  point P8 (-2.03, 0.025)
  point P9 (0, 0)
  point P10 (0, 0.785)
  point P11 (1.25, -0.785)
  point P12 (2.03, 0.025)
  point P17 (-1.27, 0.2)
  point P22 (0, 0.2)
  point P13 (-1.08, 0.01)
  point P23 (1.08, 0.01)
  point P14 (-1.46, 0.01)
  point P24 (1.46, 0.01)
  point P15 (-1.46, 0.39)
  point P25 (1.46, 0.39)
  point P16 (-1.08, 0.39)
  point P26 (1.08, 0.39)
  point P4 (-2.03, 0.785)
  point P5 (2.03, 0.785)
  point P3 (-2.03, -0.785)
  horizontal L1
  perpendicular L1 L2
  parallel L1 L3
  parallel L2 L4
  coincident L5 P6
  coincident L6 P6
  coincident P1 P6
  coincident L1 P7
  coincident L2 P8
  coincident P1 P9
  midpoint L3 P10
  symmetric P7 L8 P11
  symmetric P8 L8 P12
  horizontal L10
  perpendicular L10 L11
  parallel L10 L12
  parallel L11 L13
  coincident L14 P17
  coincident L15 P17
  horizontal L16
  perpendicular L16 L17
  parallel L16 L18
  parallel L17 L19
  coincident L20 P22
  coincident L21 P22
  vertical P1 P22
  horizontal P17 P22
  equal L12 L18
  equal L13 L17
  symmetric L8 P13 P23
  symmetric L8 P14 P24
  symmetric L8 P15 P25
  symmetric L8 P16 P26
  dimension "d1" distance P4 P5 = 4.06
  dimension "d2" distance P3 P4 = 1.57
  dimension "d3" distance L3 P8 = 0.76
  dimension "d4" distance P1 P7 = 1.25 (= "( 2.5 / 2 ) * 1 mm")
  dimension "d5" distance P15 P16 = 0.38
  dimension "d6" distance P17 P22 = 1.27
  dimension "d7" distance P6 P22 = 0.2
  dimension "d8" distance P13 P16 = 0.38
extrude "Extrude1" new body sketch "Top Profile" profile of L1 L2 L3 L4 L7 L9 L10 L11 L12 L13 L16 L17 L18 L19 along normal blind 3
extrude "Extrude2" add sketch "Top Profile" profile of L10 L11 L12 L13 L16 L17 L18 L19 L22 L23 L24 L25 against normal blind 5.5 (magnitude of "-15.5 mm + 10 mm")
sketch "Mag Slot (South should face this way)" plane through (0, -0.785, 0) normal (0, -1, 0) x axis (1, 0, 0)
  line L1 (1.25, 0) -> (-1.25, 0)
  line L2 (1.25, 3) -> (1.25, 0)
  line L3 (-1.25, 3) -> (1.25, 3)
  line L4 (-1.25, 0) -> (-1.25, 3)
  line L5 (-1.25, 1.69) -> (1.25, 1.69)
  line L6 (-1.25, 1.79) -> (-1.25, 1.69)
  line L7 (1.25, 1.79) -> (-1.25, 1.79)
  line L8 (1.25, 1.69) -> (1.25, 1.79)
  line L9 (-1.25, 1.79) -> (1.25, 1.69)
  line L10 (1.25, 1.79) -> (-1.25, 1.69)
  point P10 (0, 1.74)
  point P11 (0, 0)
  point P9 (1.25, 1.79)
  point P6 (1.25, 1.69)
  point P12 (0, 0)
  horizontal L5
  perpendicular L5 L6
  parallel L5 L7
  parallel L6 L8
  coincident L9 P10
  coincident L10 P10
  vertical P10 P11
  coincident L2 P9
  dimension "d13" distance P6 P9 = 0.1
  dimension "d14" distance P10 P12 = 1.74
extrude "Extrude3" cut sketch "Mag Slot (South should face this way)" profile of L2 L4 L5 L6 L7 L8 against normal blind 0.1

design "ULN2003 Stepper Driver v18"
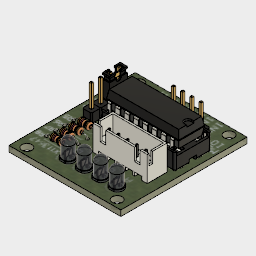
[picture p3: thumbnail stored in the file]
parameter "dip16_package_length" = 20
parameter "dip16_package_width" = 7.1
parameter "dip16_package_height" = 4.6
parameter "dip16_above_board" = 0.51
parameter "dip16_lead_thick" = 0.25
parameter "dip16_lead_width" = 1.35 comment "1.14 - 1.65"
parameter "dip16_lead_spacing" = 2.54
parameter "dip16_lead_extension" = 0.26
parameter "dip16_package_taper" = 10
parameter "dip16_lead_foot_length" = 3.3 comment "0.41 - 0.89"
parameter "dip16_lead_foot_angle" = 1 comment "0 - 8"
parameter "dip16_lead_upper_length" = 2.685 (= "dip16_above_board + ( dip16_package_height - dip16_lead_thick ) / 2")
parameter "dip16_lead_foot_width" = 0.45 comment "0.36 - 0.66"
parameter "dip16_socket_length" = 20.32 comment "tol + 0 - 0.05 mm"
parameter "dip16_socket_width" = 10.04 (= "0.4 in - 0.12 mm") comment "tol + 0.1 - 0.05 mm"
parameter "dip16_socket_height" = 5.04
parameter "dip16_socket_lead_thick" = 0.16
parameter "dip16_socket_lead_width" = 1.25
parameter "dip16_socket_lead_foot_width" = 0.62
parameter "dip16_socket_lead_length" = 8.2
parameter "dip16_socket_above_board" = 0.25
parameter "dip16_socket_lead_spacing" = 2.54
parameter "dip16_socket_length_1" = 20.32 comment "tol + 0 - 0.05 mm"
parameter "dip16_socket_width_1" = 10.04 (= "0.4 in - 0.12 mm") comment "tol + 0.1 - 0.05 mm"
parameter "dip16_socket_height_1" = 5.04
parameter "dip16_socket_lead_thick_1" = 0.16
parameter "dip16_socket_lead_width_1" = 1.25
parameter "dip16_socket_lead_foot_width_1" = 0.62
parameter "dip16_socket_lead_length_1" = 8.2
parameter "dip16_socket_above_board_1" = 0.25
parameter "dip16_socket_lead_spacing_1" = 2.54
base_feature "Base Feature1"
base_feature "Base Feature1"
base_feature "Base Feature1"
extrude "Extrude1" sketch "unnamed" blind 2.54
sketch "Sketch1"
  dimension "d5" = 0.635
extrude "Extrude2" sketch "Sketch1" blind -2.54
sketch "Sketch1"
  dimension "d8_1" = 0.635
  dimension "d9_2" = 0.635
extrude "Extrude1" sketch "Sketch1" blind 8.89 named "d10_2" second side blind 2.54 named "d12_2"
chamfer "Chamfer1" distance 0.1588 named "d13_2"
copy_paste "CutPaste1"
copy_paste "CutPaste2"
rectangular_pattern "R-Pattern1" uSpaceDistance 2.54 named "d16_2" vSpaceDistance 2.54 named "d17_2"
base_feature "Base Feature1"
extrude "Extrude1" sketch "unnamed" blind 2.54 named "d1_1"
sketch "Sketch1"
  dimension "d5_1" = 0.635
extrude "Extrude2" sketch "Sketch1" blind -2.54 named "d6_1"
sketch "Sketch1"
  dimension "d8_2" = 0.635
  dimension "d9_3" = 0.635
extrude "Extrude1" sketch "Sketch1" blind 8.89 named "d10_3" second side blind 2.54 named "d12_3"
chamfer "Chamfer1" distance 0.1588 named "d13_3"
copy_paste "CutPaste1"
copy_paste "CutPaste2"
rectangular_pattern "R-Pattern1" countU 4 (= "pins_wide_1") named "d14_3" uSpaceDistance 2.54 named "d16_3" vSpaceDistance 2.54 named "d17_3"
base_feature "Base Feature1"
position "Position1"
copy_paste "CopyPaste1"
copy_paste "CopyPaste2"
copy_paste "CopyPaste3"
work_plane "WorkPlane1" AlongDistance 2.81 (= "dip16_above_board + dip16_package_height / 2")
sketch "Sketch1"
  dimension "d13" = 7.1 (= "dip16_package_width")
  dimension "d14" = 20 (= "dip16_package_length")
extrude "Extrude1" sketch "Sketch1" blind -0.125 (= "-dip16_lead_thick / 2")
sketch "Sketch2"
extrude "Extrude2" sketch "Sketch2" blind 2.175 (= "( dip16_package_height - dip16_lead_thick ) / 2") taper -10 (= "-dip16_package_taper")
mirror "Mirror1"
combine "Combine1"
work_plane "WorkPlane1" AlongDistance -1.27 (= "-dip16_lead_spacing / 2")
sketch "Sketch1"
  dimension "d23" = 0.08
  dimension "d24" = 2.685 (= "dip16_above_board + ( dip16_package_height - dip16_lead_thick ) / 2")
  dimension "d28" = 0.15
  dimension "d29" = 3.55 (= "dip16_package_width / 2")
  dimension "d53" = 91 (= "90 deg + dip16_lead_foot_angle")
  dimension "d55" = 0.26 (= "dip16_lead_extension")
  dimension "d56" = 0.25 (= "dip16_lead_thick")
  dimension "d57" = 0.43 (= "dip16_above_board - d23")
extrude "Extrude1" sketch "Sketch1" blind 0.675 (= "dip16_lead_width / 2")
sketch "Sketch2"
  dimension "d58" = 45
  dimension "d59" = 2.175 (= "dip16_lead_upper_length - dip16_above_board")
  dimension "d60" = 3.3 (= "dip16_lead_foot_length")
  dimension "d61" = 0.45 (= "dip16_lead_foot_width")
extrude "Extrude2" sketch "Sketch2" blind -0.25 (= "-dip16_lead_thick")
extrude "Extrude3" sketch "Sketch2" blind 0.125 (= "dip16_lead_thick / 2")
fillet "Fillet1" radius 0.05
rectangular_pattern "R-Pattern1" uSpaceDistance 2.54 (= "dip16_lead_spacing") vSpaceDistance 0
mirror "Mirror1"
sketch "Sketch3"
  dimension "d74" = 2
  dimension "d75" = 1
extrude "Extrude3" sketch "Sketch3" blind -0.5 taper -5
sketch "Sketch2 (1)"
  dimension "d67" = 10 (= "dip16_package_length / 2")
  dimension "d68" = 0.82 (= "( dip16_lead_spacing ) / 2 - dip16_lead_foot_width")
  dimension "d69" = 5.11 (= "dip16_above_board + dip16_package_height")
  dimension "d70" = 3.3 (= "dip16_lead_foot_length")
extrude "Extrude4" sketch "Sketch2 (1)" no distance stored
base_feature "Base Feature1"
copy_paste "CopyPaste1"
copy_paste "CopyPaste2"
copy_paste "CopyPaste3"
copy_paste "CopyPaste4"
sketch "Sketch1"
  dimension "d7" = 31
  dimension "d8" = 35
  dimension "d9" = 2.75
  dimension "d10" = 3
  dimension "d11" = 2
  dimension "d22" = 25 (= "d7 - 2 * d10")
  dimension "d25" = -31 (= "-d8 + 2 * d11")
extrude "Extrude1" sketch "Sketch1" blind 1.6
sketch "Sketch2"
  dimension "d30" = 0.8
  dimension "d36" = -2.54
  dimension "d37" = 7.62
  dimension "d38" = 2.54
  dimension "d39" = 10
  dimension "d40" = 0.8
  dimension "d41" = 6.5
  dimension "d42" = 9.5
  dimension "d45" = -2.54
  dimension "d46" = 0
  dimension "d52" = 0.8
  dimension "d54" = 5
  dimension "d62" = 9.5
  dimension "d80" = 0
  dimension "d81" = 2.54
  dimension "d82" = 0.8
  dimension "d83" = 3
  dimension "d84" = 20
  dimension "d87" = -6.35
  dimension "d88" = 2.54
  dimension "d89" = 0.8
  dimension "d92" = -2.54
  dimension "d93" = 0
  dimension "d94" = 5
  dimension "d95" = 12
  dimension "d96" = 0.8
  dimension "d99" = -4.445
  dimension "d100" = 1.75
  dimension "d101" = 4
  dimension "d102" = 6
extrude "Extrude2" sketch "Sketch2" blind -2
chamfer "Chamfer1" distance 0.1
position "Position2"
sketch "Sketch1"
  dimension "d106" = 0.5
  dimension "d107" = 1
  dimension "d108" = 2
  dimension "d116" = 1
work_plane "WorkPlane3"
sketch "Sketch2"
  circle C1 centre (0, -2.5) radius 0.1
  dimension "d113" diameter C1 = 0.2
sweep "Sweep1" sketch "Sketch2"
work_plane "WorkPlane2" AlongDistance 6
work_plane "WorkPlane1"
mirror "Mirror1"
position "Position3"
sketch "Sketch1"
  dimension "d9_1" = 2.51 (= "dip16_socket_width_1 * 0.25")
  dimension "d10_1" = 1
  dimension "d11_1" = 19.32 (= "dip16_socket_length_1 - 1 mm")
extrude "Extrude1" sketch "Sketch1" blind 0.25 (= "dip16_socket_above_board_1") named "d12_1"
